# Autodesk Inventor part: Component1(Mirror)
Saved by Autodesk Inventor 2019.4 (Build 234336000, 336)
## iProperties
Created: 2020-06
Part Number: Component1(Mirror)
Material: Generic
Document SubType Name: Modeling
Designer: Administrator
Density: 1 g/cm^3
Appearance: Default
Title: Component1(Mirror)
Author: Administrator
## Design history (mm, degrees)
